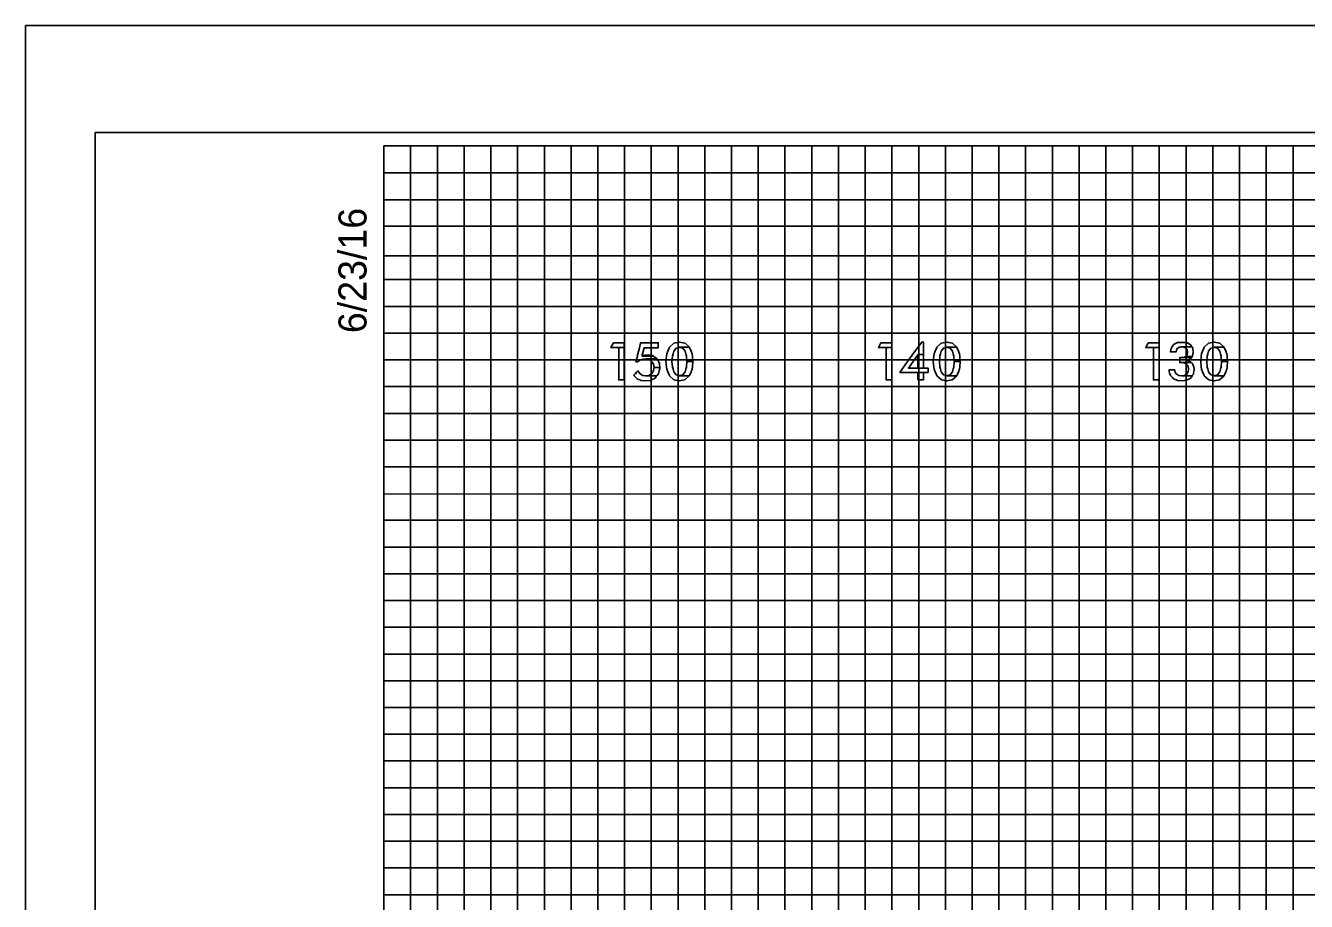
# Model space of a CAD drawing. Extents: x -13 to 323, y -5 to 1431.
# Drawn here: x -13.4 to 34.5, y 1061.75 to 1094.5 of the extents above; entities that cross this region are included whole.
import ezdxf

# ---------------------------------------------------------------- set-up
doc = ezdxf.new("R2010")
doc.units = 0
for name, color, linetype in [('Prop XS Offset Labels', 7, 'Continuous'), ('Sheet Cross Section CELL', 7, 'Continuous'), ('Sheet Cross Section Grid Major CELL', 7, 'Continuous'), ('Sheet Cross Section Grid Middle CELL', 7, 'Continuous'), ('Sheet Cross Section Grid Minor 1 CELL', 7, 'Continuous'), ('Sheet Cross Section Grid Minor 2 CELL', 7, 'Continuous'), ('Sheet Cutting Line CELL', 7, 'Continuous'), ('Sheet DOT Grid CELL', 7, 'Continuous'), ('Sheet Plot Border Inside CELL', 7, 'Continuous'), ('Sheet Plot Border Outside CELL', 7, 'Continuous')]:
    doc.layers.add(name, color=color, linetype=linetype)

msp = doc.modelspace()

# ---------------------------------------------------------------- linework, layer by layer
at = {"layer": 'Prop XS Offset Labels'}
for points in [[(8.581, 1082.641), (8.492, 1082.459), (8.99, 1082.459), (8.99, 1082.641)], [(9.427, 1081.94), (9.424, 1081.928), (9.495, 1081.928), (9.508, 1081.94), (9.524, 1081.954), (9.595, 1081.997), (9.627, 1082.007), (9.697, 1082.029), (9.811, 1082.035), (10.219, 1082.035), (10.211, 1082.05), (10.076, 1082.145), (9.655, 1082.145), (9.658, 1082.158), (9.658, 1082.158), (9.663, 1082.178), (9.738, 1082.456), (10.263, 1082.456), (10.263, 1082.641), (9.6, 1082.641), (9.554, 1082.456), (9.486, 1082.178), (9.481, 1082.158), (9.478, 1082.145), (9.454, 1082.05), (9.451, 1082.035), (9.449, 1082.029), (9.444, 1082.007), (9.441, 1081.997), (9.431, 1081.954)], [(10.851, 1081.255), (11.051, 1081.214), (11.245, 1081.255), (11.256, 1081.257), (11.422, 1081.409), (11.047, 1081.409), (11.038, 1081.411), (11.033, 1081.413), (10.928, 1081.442), (10.841, 1081.555), (10.841, 1081.556), (10.841, 1081.556), (10.813, 1081.657), (10.813, 1081.659), (10.793, 1081.732), (10.792, 1081.736), (10.774, 1081.939), (10.774, 1081.941), (10.774, 1081.943), (10.792, 1082.145), (10.812, 1082.222), (10.813, 1082.224), (10.839, 1082.322), (10.84, 1082.325), (10.928, 1082.44), (11.041, 1082.469), (11.045, 1082.47), (11.055, 1082.473), (11.425, 1082.473), (11.262, 1082.622), (11.254, 1082.624), (11.053, 1082.668), (11.053, 1082.668), (10.845, 1082.624), (10.843, 1082.622), (10.681, 1082.473), (10.678, 1082.47), (10.678, 1082.469), (10.665, 1082.44), (10.618, 1082.325), (10.617, 1082.322), (10.577, 1082.224), (10.576, 1082.222), (10.568, 1082.145), (10.547, 1081.943), (10.547, 1081.941), (10.547, 1081.939), (10.567, 1081.736), (10.568, 1081.732), (10.575, 1081.659), (10.575, 1081.657), (10.616, 1081.556), (10.617, 1081.555), (10.663, 1081.442), (10.675, 1081.413), (10.676, 1081.411), (10.679, 1081.409), (10.848, 1081.257)], [(18.581, 1082.641), (18.492, 1082.459), (18.99, 1082.459), (18.99, 1082.641)], [(19.411, 1081.693), (19.297, 1081.534), (20.35, 1081.534), (20.35, 1081.693), (19.618, 1081.693), (19.878, 1082.059), (19.935, 1082.139), (19.977, 1082.199), (20.179, 1082.199), (20.179, 1082.668), (20.114, 1082.668), (19.775, 1082.199), (19.733, 1082.139), (19.675, 1082.059)], [(20.851, 1081.255), (21.051, 1081.214), (21.245, 1081.255), (21.256, 1081.257), (21.422, 1081.409), (21.047, 1081.409), (21.038, 1081.411), (21.033, 1081.413), (20.928, 1081.442), (20.841, 1081.555), (20.841, 1081.556), (20.841, 1081.556), (20.813, 1081.657), (20.813, 1081.659), (20.793, 1081.732), (20.792, 1081.736), (20.774, 1081.939), (20.774, 1081.941), (20.774, 1081.943), (20.792, 1082.145), (20.812, 1082.222), (20.813, 1082.224), (20.839, 1082.322), (20.84, 1082.325), (20.928, 1082.44), (21.041, 1082.469), (21.045, 1082.47), (21.055, 1082.473), (21.425, 1082.473), (21.262, 1082.622), (21.254, 1082.624), (21.053, 1082.668), (21.053, 1082.668), (20.845, 1082.624), (20.843, 1082.622), (20.681, 1082.473), (20.678, 1082.47), (20.678, 1082.469), (20.665, 1082.44), (20.618, 1082.325), (20.617, 1082.322), (20.577, 1082.224), (20.576, 1082.222), (20.568, 1082.145), (20.547, 1081.943), (20.547, 1081.941), (20.547, 1081.939), (20.567, 1081.736), (20.567, 1081.732), (20.575, 1081.659), (20.575, 1081.657), (20.616, 1081.556), (20.617, 1081.555), (20.663, 1081.442), (20.675, 1081.413), (20.676, 1081.411), (20.679, 1081.409), (20.848, 1081.257)], [(28.581, 1082.641), (28.492, 1082.459), (28.99, 1082.459), (28.99, 1082.641)], [(29.42, 1082.315), (29.418, 1082.297), (29.626, 1082.297), (29.627, 1082.315), (29.639, 1082.365), (29.64, 1082.372), (29.641, 1082.373), (29.683, 1082.433), (29.688, 1082.436), (29.696, 1082.44), (29.748, 1082.47), (29.785, 1082.476), (29.795, 1082.478), (29.835, 1082.485), (30.217, 1082.485), (30.165, 1082.561), (30.129, 1082.582), (30.128, 1082.582), (30.023, 1082.644), (29.982, 1082.65), (29.69, 1082.65), (29.678, 1082.644), (29.553, 1082.582), (29.536, 1082.561), (29.471, 1082.485), (29.466, 1082.478), (29.465, 1082.476), (29.463, 1082.47), (29.452, 1082.44), (29.45, 1082.436), (29.449, 1082.433), (29.428, 1082.373), (29.427, 1082.372), (29.425, 1082.365)], [(29.853, 1082.668), (29.69, 1082.65), (29.982, 1082.65)], [(30.851, 1081.255), (31.051, 1081.214), (31.245, 1081.255), (31.256, 1081.257), (31.422, 1081.409), (31.047, 1081.409), (31.038, 1081.411), (31.033, 1081.413), (30.928, 1081.442), (30.841, 1081.555), (30.841, 1081.556), (30.841, 1081.556), (30.813, 1081.657), (30.813, 1081.659), (30.793, 1081.732), (30.792, 1081.736), (30.774, 1081.939), (30.774, 1081.941), (30.774, 1081.943), (30.792, 1082.145), (30.812, 1082.222), (30.813, 1082.224), (30.839, 1082.322), (30.84, 1082.325), (30.928, 1082.44), (31.041, 1082.469), (31.045, 1082.47), (31.055, 1082.473), (31.425, 1082.473), (31.262, 1082.622), (31.254, 1082.624), (31.053, 1082.668), (31.053, 1082.668), (30.845, 1082.624), (30.843, 1082.622), (30.681, 1082.473), (30.678, 1082.47), (30.678, 1082.469), (30.665, 1082.44), (30.618, 1082.325), (30.617, 1082.322), (30.577, 1082.224), (30.576, 1082.222), (30.568, 1082.145), (30.547, 1081.943), (30.547, 1081.941), (30.547, 1081.939), (30.567, 1081.736), (30.567, 1081.732), (30.575, 1081.659), (30.575, 1081.657), (30.616, 1081.556), (30.617, 1081.555), (30.663, 1081.442), (30.675, 1081.413), (30.676, 1081.411), (30.679, 1081.409), (30.848, 1081.257)], [(8.781, 1082.459), (8.781, 1081.25), (8.99, 1081.25), (8.99, 1082.459)], [(9.692, 1082.158), (9.655, 1082.145), (10.076, 1082.145), (10.058, 1082.158), (9.961, 1082.178), (9.75, 1082.178)], [(9.888, 1082.192), (9.75, 1082.178), (9.96, 1082.178), (9.888, 1082.192)], [(11.312, 1082.145), (11.328, 1081.943), (11.555, 1081.943), (11.536, 1082.145), (11.528, 1082.222), (11.527, 1082.224), (11.527, 1082.224), (11.488, 1082.322), (11.488, 1082.322), (11.487, 1082.325), (11.441, 1082.44), (11.44, 1082.44), (11.429, 1082.469), (11.428, 1082.47), (11.425, 1082.473), (11.055, 1082.473), (11.065, 1082.47), (11.068, 1082.469), (11.175, 1082.44), (11.262, 1082.325), (11.265, 1082.322), (11.291, 1082.224), (11.291, 1082.222)], [(18.781, 1082.459), (18.781, 1081.25), (18.99, 1081.25), (18.99, 1082.459)], [(19.97, 1082.059), (19.97, 1081.693), (20.179, 1081.693), (20.179, 1082.059), (20.179, 1082.139), (20.179, 1082.199), (19.977, 1082.199), (19.973, 1082.139)], [(21.312, 1082.145), (21.328, 1081.943), (21.555, 1081.943), (21.536, 1082.145), (21.528, 1082.222), (21.527, 1082.224), (21.527, 1082.224), (21.488, 1082.322), (21.488, 1082.322), (21.487, 1082.325), (21.441, 1082.44), (21.44, 1082.44), (21.429, 1082.469), (21.428, 1082.47), (21.425, 1082.473), (21.055, 1082.473), (21.065, 1082.47), (21.068, 1082.469), (21.175, 1082.44), (21.262, 1082.325), (21.265, 1082.322), (21.291, 1082.224), (21.291, 1082.222)], [(28.781, 1082.459), (28.781, 1081.25), (28.99, 1081.25), (28.99, 1082.459)], [(29.765, 1081.956), (29.765, 1081.9), (30.194, 1081.9), (30.119, 1081.956), (30.029, 1081.983), (30.095, 1082), (30.181, 1082.053), (30.2, 1082.084), (30.201, 1082.085), (30.207, 1082.095), (29.915, 1082.095), (29.83, 1082.085), (29.765, 1082.084), (29.765, 1082.053), (29.765, 1082), (29.765, 1081.983)], [(30.007, 1082.155), (29.988, 1082.131), (30.23, 1082.131), (30.246, 1082.155), (30.254, 1082.201), (30.271, 1082.289), (30.272, 1082.295), (30.272, 1082.297), (30.269, 1082.315), (30.26, 1082.365), (30.259, 1082.372), (30.259, 1082.373), (30.259, 1082.373), (30.249, 1082.433), (30.248, 1082.436), (30.248, 1082.44), (30.227, 1082.47), (30.223, 1082.476), (30.222, 1082.478), (30.217, 1082.485), (29.835, 1082.485), (29.901, 1082.478), (29.919, 1082.476), (29.931, 1082.47), (29.986, 1082.44), (29.995, 1082.436), (29.997, 1082.433), (30.04, 1082.373), (30.04, 1082.372), (30.042, 1082.365), (30.051, 1082.315), (30.054, 1082.297), (30.055, 1082.295), (30.056, 1082.289), (30.041, 1082.201)], [(29.988, 1082.131), (29.915, 1082.095), (30.207, 1082.095), (30.23, 1082.131)], [(31.312, 1082.145), (31.328, 1081.943), (31.555, 1081.943), (31.536, 1082.145), (31.528, 1082.222), (31.527, 1082.224), (31.527, 1082.224), (31.488, 1082.322), (31.488, 1082.322), (31.487, 1082.325), (31.441, 1082.44), (31.44, 1082.44), (31.429, 1082.469), (31.428, 1082.47), (31.425, 1082.473), (31.055, 1082.473), (31.065, 1082.47), (31.068, 1082.469), (31.175, 1082.44), (31.262, 1082.325), (31.265, 1082.322), (31.291, 1082.224), (31.291, 1082.222)], [(9.626, 1081.233), (9.762, 1081.214), (9.959, 1081.233), (9.968, 1081.237), (10.091, 1081.297), (10.091, 1081.297), (10.141, 1081.321), (10.185, 1081.375), (10.204, 1081.399), (9.793, 1081.399), (9.683, 1081.418), (9.682, 1081.419), (9.679, 1081.42), (9.596, 1081.466), (9.586, 1081.477), (9.58, 1081.483), (9.58, 1081.483), (9.529, 1081.535), (9.497, 1081.585), (9.497, 1081.585), (9.451, 1081.535), (9.404, 1081.483), (9.399, 1081.477), (9.39, 1081.466), (9.348, 1081.42), (9.347, 1081.419), (9.348, 1081.418), (9.363, 1081.399), (9.382, 1081.375), (9.445, 1081.321), (9.474, 1081.297), (9.598, 1081.237)], [(9.424, 1081.928), (9.482, 1081.916), (9.495, 1081.928)], [(9.9, 1081.418), (9.793, 1081.399), (10.204, 1081.399), (10.22, 1081.418), (10.221, 1081.419), (10.222, 1081.42), (10.222, 1081.42), (10.259, 1081.466), (10.268, 1081.477), (10.27, 1081.483), (10.284, 1081.535), (10.299, 1081.59), (10.322, 1081.674), (10.318, 1081.721), (10.105, 1081.721), (10.097, 1081.674), (10.082, 1081.59), (10.047, 1081.535), (10.014, 1081.483), (10.004, 1081.477), (9.987, 1081.466), (9.913, 1081.42), (9.905, 1081.419)], [(10.083, 1081.841), (10.105, 1081.721), (10.318, 1081.721), (10.307, 1081.841), (10.307, 1081.841), (10.303, 1081.881), (10.284, 1081.916), (10.278, 1081.928), (10.271, 1081.94), (10.263, 1081.954), (10.24, 1081.997), (10.235, 1082.007), (10.223, 1082.029), (10.219, 1082.035), (9.811, 1082.035), (9.838, 1082.029), (9.928, 1082.007), (9.943, 1081.997), (10.003, 1081.954), (10.024, 1081.94), (10.031, 1081.928), (10.038, 1081.916), (10.059, 1081.881)], [(11.058, 1081.411), (11.047, 1081.409), (11.422, 1081.409), (11.425, 1081.411), (11.426, 1081.413), (11.438, 1081.442), (11.485, 1081.555), (11.485, 1081.556), (11.527, 1081.657), (11.528, 1081.659), (11.535, 1081.732), (11.535, 1081.736), (11.555, 1081.939), (11.556, 1081.941), (11.555, 1081.943), (11.328, 1081.943), (11.328, 1081.941), (11.328, 1081.939), (11.312, 1081.736), (11.312, 1081.732), (11.292, 1081.659), (11.291, 1081.657), (11.264, 1081.556), (11.263, 1081.555), (11.175, 1081.442), (11.063, 1081.413)], [(21.058, 1081.411), (21.047, 1081.409), (21.422, 1081.409), (21.425, 1081.411), (21.426, 1081.413), (21.438, 1081.442), (21.485, 1081.555), (21.485, 1081.556), (21.527, 1081.657), (21.528, 1081.659), (21.535, 1081.732), (21.535, 1081.736), (21.555, 1081.939), (21.556, 1081.941), (21.555, 1081.943), (21.328, 1081.943), (21.328, 1081.941), (21.328, 1081.939), (21.312, 1081.736), (21.312, 1081.732), (21.292, 1081.659), (21.291, 1081.657), (21.264, 1081.556), (21.263, 1081.555), (21.175, 1081.442), (21.063, 1081.413)], [(29.677, 1081.229), (29.854, 1081.214), (29.936, 1081.229), (30.042, 1081.248), (30.123, 1081.297), (30.187, 1081.336), (30.228, 1081.399), (30.229, 1081.401), (29.849, 1081.401), (29.72, 1081.416), (29.711, 1081.423), (29.639, 1081.471), (29.628, 1081.479), (29.626, 1081.482), (29.608, 1081.516), (29.584, 1081.562), (29.584, 1081.567), (29.58, 1081.62), (29.58, 1081.625), (29.361, 1081.625), (29.362, 1081.62), (29.369, 1081.567), (29.37, 1081.562), (29.377, 1081.516), (29.391, 1081.482), (29.392, 1081.479), (29.395, 1081.471), (29.415, 1081.423), (29.418, 1081.416), (29.425, 1081.401), (29.426, 1081.399), (29.49, 1081.336), (29.53, 1081.297), (29.635, 1081.248)], [(29.925, 1081.416), (29.849, 1081.401), (30.229, 1081.401), (30.239, 1081.416), (30.243, 1081.423), (30.243, 1081.423), (30.275, 1081.471), (30.277, 1081.479), (30.277, 1081.482), (30.283, 1081.516), (30.292, 1081.562), (30.293, 1081.567), (30.303, 1081.62), (30.297, 1081.662), (30.285, 1081.751), (30.283, 1081.763), (30.25, 1081.826), (30.223, 1081.877), (30.222, 1081.88), (30.197, 1081.898), (30.194, 1081.9), (29.81, 1081.9), (29.878, 1081.898), (29.951, 1081.88), (29.963, 1081.877), (30.033, 1081.826), (30.07, 1081.763), (30.077, 1081.751), (30.092, 1081.662), (30.088, 1081.62), (30.083, 1081.567), (30.08, 1081.562), (30.057, 1081.516), (30.039, 1081.482), (30.035, 1081.479), (30.025, 1081.471), (29.957, 1081.423)], [(31.058, 1081.411), (31.047, 1081.409), (31.422, 1081.409), (31.425, 1081.411), (31.426, 1081.413), (31.438, 1081.442), (31.485, 1081.555), (31.485, 1081.556), (31.527, 1081.657), (31.528, 1081.659), (31.535, 1081.732), (31.535, 1081.736), (31.555, 1081.939), (31.556, 1081.941), (31.555, 1081.943), (31.328, 1081.943), (31.328, 1081.941), (31.328, 1081.939), (31.312, 1081.736), (31.312, 1081.732), (31.292, 1081.659), (31.291, 1081.657), (31.264, 1081.556), (31.263, 1081.555), (31.175, 1081.442), (31.063, 1081.413)], [(19.97, 1081.534), (19.97, 1081.25), (20.179, 1081.25), (20.179, 1081.534)]]:
    msp.add_lwpolyline(points, close=True, dxfattribs=at)
at = {"layer": 'Sheet Cross Section CELL'}
msp.add_lwpolyline([(320, 1090), (0, 1090), (0, 880), (320, 880)], close=True, dxfattribs=at)
at = {"layer": 'Sheet Cross Section Grid Major CELL'}
for p, q in [((10, 1090), (0, 1090)), ((10, 880), (10, 1090)), ((30, 1090), (20, 1090)), ((20, 1090), (20, 880)), ((30, 880), (30, 1090))]:
    msp.add_line(p, q, dxfattribs=at)
msp.add_lwpolyline([(0, 1080), (320, 1080), (320, 1070), (0, 1070)], dxfattribs=at)
at = {"layer": 'Sheet Cross Section Grid Middle CELL'}
for points in [[(0, 1090), (5, 1090), (5, 880)], [(15, 880), (15, 1090), (25, 1090), (25, 880)], [(0, 1085), (275, 1085)], [(0, 1065), (320, 1065), (320, 1075), (0, 1075)]]:
    msp.add_lwpolyline(points, dxfattribs=at)
at = {"layer": 'Sheet Cross Section Grid Minor 1 CELL'}
for p, q in [((0, 1089), (260, 1089)), ((260, 1087.98), (0, 1087.98)), ((0, 1087.98), (0, 1087)), ((0, 1087), (260, 1087)), ((260, 1085.89), (0, 1085.89)), ((0, 1085.89), (0, 1084)), ((0, 1084), (320, 1084))]:
    msp.add_line(p, q, dxfattribs=at)
for points in [[(0, 1083), (270, 1083), (320, 1083), (320, 1082), (0, 1082)], [(0, 1081), (320, 1081), (320, 1079), (0, 1079)], [(0, 1078), (320, 1078), (320, 1077), (0, 1076.98)], [(0, 1076), (320, 1076), (320, 1074), (0, 1074)], [(0, 1073), (320, 1073), (320, 1072), (0, 1072)], [(0, 1071), (320, 1071), (320, 1069), (0, 1069)], [(0, 1068), (320, 1068), (320, 1067), (0, 1067)], [(0, 1066), (320, 1066), (320, 1064), (0, 1064)], [(0, 1063), (320, 1063), (320, 1062), (0, 1062)]]:
    msp.add_lwpolyline(points, dxfattribs=at)
at = {"layer": 'Sheet Cross Section Grid Minor 2 CELL'}
for points in [[(0, 880), (1, 880), (1, 1090), (2, 1090), (2, 880)], [(2, 880), (3, 880), (3, 1090), (4, 1090), (4, 880)], [(5, 880), (6, 880), (6, 1090), (7, 1090), (7, 880)], [(7, 880), (8, 880), (8, 1090), (9, 1090), (9, 880)], [(10, 880), (11, 880), (11, 1090), (12, 1090), (12, 880)], [(12, 880), (13, 880), (13, 1090), (14, 1090), (14, 880)], [(15, 880), (16, 880), (16, 1090), (17, 1090), (17, 880)], [(17, 880), (18, 880), (18, 1090), (19, 1090), (19, 880)], [(20, 880), (21, 880), (21, 1090), (22, 1090), (22, 880)], [(22, 880), (23, 880), (23, 1090), (24, 1090), (24, 880)], [(25, 880), (26, 880), (26, 1090), (27, 1090), (27, 880)], [(27, 880), (28, 880), (28, 1090), (29, 1090), (29, 880)], [(30, 880), (31, 880), (31, 1090), (32, 1090), (32, 880)], [(32, 880), (33, 880), (33, 1090), (34, 1090), (34, 880)]]:
    msp.add_lwpolyline(points, dxfattribs=at)
at = {"layer": 'Sheet Cutting Line CELL'}
for p, q in [((323.3, 1094.5), (-13.4, 1094.5)), ((-13.4, 1094.5), (-13.4, 875.5))]:
    msp.add_line(p, q, dxfattribs=at)
at = {"layer": 'Sheet DOT Grid CELL'}
for p, q in [((10, 880), (10, 1090)), ((20, 880), (20, 1090)), ((30, 880), (30, 1090)), ((0, 1080), (320, 1080)), ((0, 1070), (320, 1070))]:
    msp.add_line(p, q, dxfattribs=at)
at = {"layer": 'Sheet Plot Border Inside CELL'}
msp.add_lwpolyline([(-10.8, 879.5), (322.4, 879.5), (322.4, 1090.5), (-10.8, 1090.5)], close=True, dxfattribs=at)
at = {"layer": 'Sheet Plot Border Outside CELL'}
msp.add_lwpolyline([(-13.4, 875.5), (323.3, 875.5), (323.3, 1094.5), (-13.4, 1094.5)], close=True, dxfattribs=at)

# ---------------------------------------------------------------- texts
at = {"layer": 'Sheet Cross Section CELL'}
msp.add_text('6/23/16', height=1.05, rotation=90, dxfattribs=at).set_placement((-0.65, 1083))

doc.saveas('drawing.dxf')
